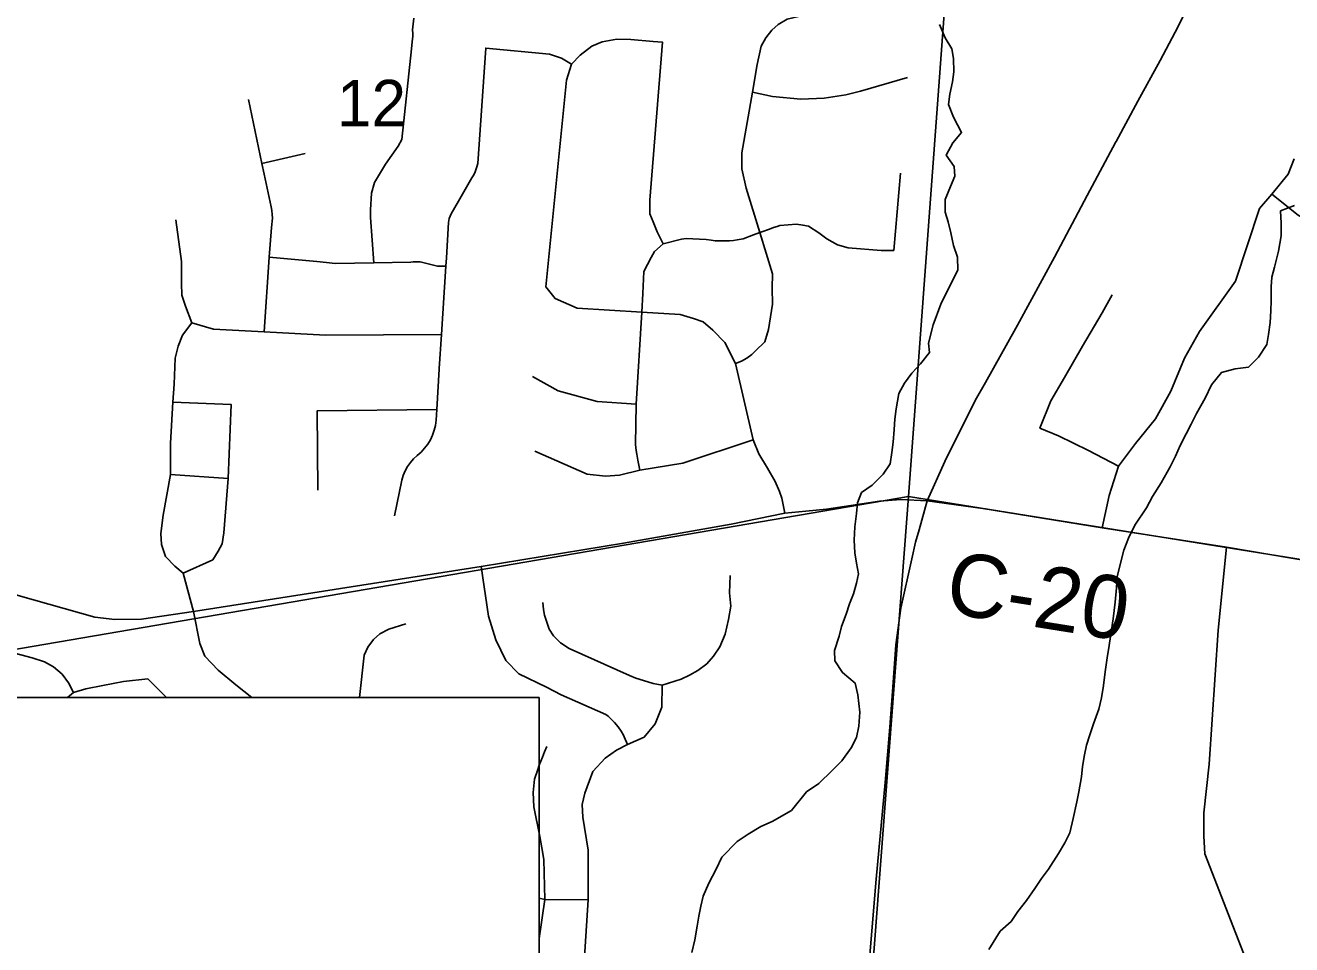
# Model space of a CAD drawing. Extents: x 0 to 34, y 0 to 22.
# Drawn here: x 3.964 to 5.107, y 19.14 to 19.97 of the extents above; entities that cross this region are included whole.
import ezdxf

# ---------------------------------------------------------------- set-up
doc = ezdxf.new("R2010")
doc.units = 0
for name, color, linetype in [('GM_X_County_Road', 7, 'Continuous'), ('GM_X_County_Road_Text', 7, 'Continuous'), ('GM_X_Minor_River', 7, 'Continuous'), ('GM_X_Section', 7, 'Continuous'), ('GM_X_Section_Text', 7, 'Continuous'), ('GM_X_State_Route', 7, 'Continuous'), ('GM_X_Township_Road', 7, 'Continuous'), ('SH_Text', 7, 'Continuous')]:
    doc.layers.add(name, color=color, linetype=linetype)

msp = doc.modelspace()

# ---------------------------------------------------------------- linework, layer by layer
at = {"layer": 'GM_X_County_Road'}
for points in [[(4.6684, 19.5314), (4.6871, 19.5332), (4.7349, 19.5405), (4.7541, 19.5419), (4.778, 19.5406)], [(4.778, 19.5406), (4.8282, 19.5339), (4.9358, 19.5164), (5.0482, 19.4989)], [(3.722, 19.5159), (3.723, 19.5156), (3.7934, 19.4984), (3.9, 19.4714), (4.0267, 19.4358), (4.0449, 19.4335), (4.0688, 19.4339), (4.1158, 19.4408), (4.3754, 19.4815), (4.5038, 19.5025), (4.601, 19.5196), (4.6497, 19.5297), (4.6684, 19.5314)], [(5.161, 18.7471), (5.1674, 18.7519), (5.169, 18.7561), (5.1733, 18.8123), (5.1758, 18.8558), (5.1727, 18.8724), (5.1612, 18.8948), (5.1426, 18.9289), (5.0287, 19.2221), (5.0277, 19.238), (5.0278, 19.2591), (5.0324, 19.303), (5.0407, 19.4239), (5.0482, 19.4989)], [(5.0482, 19.4989), (5.2615, 19.4628), (5.4086, 19.4362), (5.7556, 19.3822), (5.814, 19.3715), (5.9052, 19.3498), (5.9474, 19.3395), (6.067, 19.3122), (6.1386, 19.2955), (6.1993, 19.2816), (6.3594, 19.2439), (6.4061, 19.2324), (6.5388, 19.202)]]:
    msp.add_lwpolyline(points, dxfattribs=at)
at = {"layer": 'GM_X_Minor_River'}
for points in [[(4.5811, 19.1955), (4.5876, 19.2083), (4.5928, 19.2191), (4.6066, 19.2331), (4.6166, 19.2397), (4.6279, 19.2469), (4.6382, 19.2512), (4.6556, 19.2613), (4.6691, 19.278), (4.6803, 19.2856), (4.6924, 19.2974), (4.7011, 19.3059), (4.7094, 19.3178), (4.7142, 19.3272), (4.7164, 19.3374), (4.7172, 19.3499), (4.7154, 19.3655), (4.713, 19.3762), (4.7015, 19.3857), (4.6946, 19.3962), (4.6945, 19.4057), (4.6987, 19.4185), (4.7008, 19.4272), (4.705, 19.4384), (4.7079, 19.4479), (4.7116, 19.4569), (4.7141, 19.4663), (4.7159, 19.475), (4.7143, 19.4845), (4.7127, 19.4937), (4.7122, 19.5051), (4.7126, 19.5173), (4.7141, 19.5294), (4.7151, 19.5389), (4.7188, 19.5482), (4.7285, 19.5548), (4.7383, 19.5648), (4.7447, 19.5741), (4.7461, 19.5843), (4.7472, 19.5938), (4.7483, 19.6051), (4.7489, 19.6146), (4.7499, 19.6237), (4.7523, 19.6377), (4.7575, 19.647), (4.7642, 19.656), (4.7721, 19.6645), (4.78, 19.6745), (4.7791, 19.6832), (4.7833, 19.6995), (4.7904, 19.7183), (4.8001, 19.7377), (4.8057, 19.749), (4.8053, 19.7607), (4.8018, 19.7711), (4.7995, 19.7826), (4.7971, 19.7925), (4.7943, 19.8014), (4.7943, 19.8128), (4.7992, 19.8244), (4.8029, 19.8338), (4.8024, 19.8426), (4.7951, 19.8527), (4.8011, 19.8639), (4.809, 19.8731), (4.8018, 19.8871), (4.7972, 19.8986), (4.7986, 19.9077), (4.8008, 19.919), (4.8022, 19.9281), (4.8018, 19.9399), (4.8002, 19.9487), (4.7944, 19.9587), (4.7891, 19.9707)], [(4.8336, 19.1357), (4.844, 19.1522), (4.8538, 19.161), (4.8597, 19.1699), (4.8676, 19.1799), (4.8752, 19.1907), (4.8811, 19.1997), (4.8875, 19.2082), (4.8966, 19.2224), (4.9022, 19.2321), (4.9067, 19.2411), (4.9097, 19.2539), (4.9132, 19.269), (4.915, 19.2781), (4.9173, 19.2917), (4.9183, 19.3008), (4.9201, 19.3114), (4.9219, 19.3201), (4.9249, 19.3295), (4.9282, 19.3393), (4.9328, 19.3528), (4.9354, 19.363), (4.9372, 19.374), (4.9387, 19.3864), (4.9406, 19.3989), (4.9424, 19.4103), (4.9444, 19.4243), (4.9458, 19.4341), (4.9478, 19.4493), (4.9489, 19.4622), (4.9496, 19.472), (4.9526, 19.4845), (4.9556, 19.4962), (4.9597, 19.5071), (4.9654, 19.5187), (4.9761, 19.5343), (4.9814, 19.5448), (4.9893, 19.5571), (4.9974, 19.5713), (5.0022, 19.581), (5.0063, 19.5908), (5.0119, 19.6013), (5.0164, 19.6099), (5.0212, 19.6196), (5.0288, 19.6334), (5.0345, 19.6454), (5.0436, 19.6565), (5.0559, 19.66), (5.0681, 19.6615), (5.0771, 19.6703), (5.0846, 19.6819), (5.086, 19.691), (5.0875, 19.7016), (5.0882, 19.7122), (5.0884, 19.7213), (5.0884, 19.7339), (5.0891, 19.7426), (5.0916, 19.7516), (5.0951, 19.766), (5.0974, 19.78), (5.0974, 19.7914), (5.0969, 19.8024), (5.1096, 19.8073)], [(4.5656, 19.1329), (4.5682, 19.1446), (4.5705, 19.1567), (4.5719, 19.1658), (4.5737, 19.1749), (4.5758, 19.1839), (4.5811, 19.1955)]]:
    msp.add_lwpolyline(points, dxfattribs=at)
at = {"layer": 'GM_X_Section'}
for points in [[(4.818, 20.3144), (4.7613, 19.5448), (3.7257, 19.3674), (3.806, 20.3918)], [(4.818, 20.3144), (5.8084, 20.2412), (5.7435, 19.3869), (4.7613, 19.5448)]]:
    msp.add_lwpolyline(points, close=True, dxfattribs=at)
for points in [[(3.7253, 19.3633), (3.7257, 19.3674), (4.7613, 19.5448), (4.6831, 18.5192), (3.6423, 18.3609), (3.6787, 18.801)], [(5.1102, 18.4472), (4.6831, 18.5192), (4.7613, 19.5448), (5.7435, 19.3869), (5.6931, 18.7255)]]:
    msp.add_lwpolyline(points, dxfattribs=at)
at = {"layer": 'GM_X_State_Route'}
for points in [[(4.9486, 19.8652), (4.9682, 19.9015), (4.9884, 19.9383), (5.0045, 19.9689), (5.014, 19.9878)], [(4.8595, 19.6992), (4.8929, 19.7608), (4.9224, 19.8164), (4.9481, 19.8643), (4.9486, 19.8652)], [(4.8306, 19.6476), (4.8581, 19.6966), (4.8595, 19.6992)], [(4.778, 19.5406), (4.7939, 19.5762), (4.8214, 19.6313), (4.8306, 19.6476)], [(4.7442, 19.3363), (4.7468, 19.3686), (4.7497, 19.4108), (4.7543, 19.4439), (4.7643, 19.4885), (4.7676, 19.5033), (4.7709, 19.5147), (4.778, 19.5406)], [(4.7164, 18.9842), (4.7189, 19.0149), (4.7243, 19.1056), (4.7319, 19.1993), (4.7401, 19.2864), (4.7442, 19.3363)]]:
    msp.add_lwpolyline(points, dxfattribs=at)
at = {"layer": 'GM_X_Township_Road'}
for p, q in [((4.1776, 19.8454), (4.2166, 19.8544)), ((4.095, 19.5644), (4.1471, 19.5608)), ((4.0916, 19.3633), (4.0747, 19.3801)), ((4.3259, 19.3633), (4.3259, 19.3636)), ((4.4279, 19.1457), (4.433, 19.181))]:
    msp.add_line(p, q, dxfattribs=at)
for points in [[(4.605, 19.6647), (4.6104, 19.6668), (4.6153, 19.6695), (4.6197, 19.6728), (4.6231, 19.6762), (4.6314, 19.6844), (4.6347, 19.6955), (4.6384, 19.7182), (4.638, 19.7327), (4.6384, 19.7457), (4.627, 19.7829), (4.6147, 19.8229), (4.6106, 19.8404), (4.6106, 19.855), (4.6203, 19.9096), (4.6246, 19.9345), (4.6283, 19.9512), (4.6324, 19.9586), (4.6377, 19.9655), (4.6435, 19.9708), (4.6516, 19.9754), (4.662, 19.978), (4.6878, 19.9824), (4.7572, 19.9878)], [(4.2786, 19.7557), (4.2756, 19.7964), (4.2756, 19.8033), (4.2765, 19.8185), (4.2792, 19.8282), (4.2892, 19.8448), (4.3007, 19.8609), (4.304, 19.8669), (4.3126, 19.9489), (4.3131, 19.9552), (4.3138, 19.9601), (4.3137, 19.9627), (4.3134, 19.966), (4.3146, 19.9765)], [(4.6497, 19.5297), (4.6467, 19.5431), (4.6447, 19.5493), (4.6408, 19.5582), (4.6338, 19.5701), (4.6262, 19.5832), (4.6211, 19.5959), (4.605, 19.6647), (4.5953, 19.6837), (4.5846, 19.6948), (4.5757, 19.7022), (4.5671, 19.7052), (4.5552, 19.7089), (4.5204, 19.7111), (4.462, 19.7148), (4.4422, 19.7234), (4.4338, 19.7338), (4.4525, 19.9206), (4.457, 19.935), (4.4647, 19.9432), (4.4755, 19.9513), (4.4847, 19.9551), (4.498, 19.9576), (4.5105, 19.9572), (4.5308, 19.9554), (4.539, 19.9549), (4.5278, 19.8122), (4.5278, 19.7999), (4.5307, 19.7925), (4.5344, 19.7836), (4.5396, 19.7728)], [(4.2973, 19.5272), (4.3038, 19.5593), (4.3051, 19.5636), (4.3069, 19.5677), (4.309, 19.5717), (4.3116, 19.5753), (4.3145, 19.5787), (4.3178, 19.5818), (4.3213, 19.5848), (4.3245, 19.5882), (4.3273, 19.5919), (4.3297, 19.5958), (4.3317, 19.6), (4.3332, 19.6044), (4.3342, 19.6089), (4.3348, 19.6135), (4.3354, 19.6232), (4.3375, 19.6597), (4.3376, 19.6602), (4.3397, 19.691), (4.3436, 19.7525), (4.3443, 19.7601), (4.346, 19.792), (4.3467, 19.7955), (4.3483, 19.7999), (4.3551, 19.8114), (4.3658, 19.8302), (4.3671, 19.8322), (4.3688, 19.8349), (4.37, 19.8378), (4.3713, 19.8414), (4.3724, 19.8452), (4.3796, 19.9495), (4.4372, 19.9441), (4.4479, 19.9403), (4.457, 19.935)], [(4.6203, 19.9096), (4.6385, 19.9057), (4.664, 19.9034), (4.685, 19.9042), (4.7045, 19.9072), (4.7179, 19.9105), (4.7602, 19.9228)], [(4.1796, 19.6934), (4.1843, 19.7606), (4.1862, 19.7874), (4.1871, 19.7958), (4.187, 19.7991), (4.1867, 19.8027), (4.1859, 19.806), (4.1797, 19.8357), (4.1776, 19.8454), (4.1654, 19.9029)], [(4.9358, 19.5164), (4.9424, 19.5455), (4.9507, 19.5719), (4.9661, 19.5926), (4.9842, 19.6149), (4.9978, 19.6398), (5.0103, 19.6696), (5.0238, 19.6937), (5.0563, 19.739), (5.0778, 19.8046), (5.0891, 19.8175), (5.1038, 19.8356), (5.1091, 19.8495)], [(4.5188, 19.5685), (4.5169, 19.5776), (4.5159, 19.5829), (4.5154, 19.5862), (4.5149, 19.5917), (4.5155, 19.6279), (4.5204, 19.7111), (4.5214, 19.7279), (4.5222, 19.7479), (4.5289, 19.7605), (4.5318, 19.7657), (4.5396, 19.7728), (4.5562, 19.7769), (4.5605, 19.7775), (4.5787, 19.7766), (4.583, 19.776), (4.5866, 19.7756), (4.5912, 19.7754), (4.5932, 19.7754), (4.5964, 19.7754), (4.5996, 19.7756), (4.6031, 19.7759), (4.6064, 19.7763), (4.6118, 19.7773), (4.6212, 19.7808), (4.627, 19.7829), (4.6288, 19.7836), (4.6358, 19.7861), (4.6393, 19.7874), (4.6425, 19.7885), (4.645, 19.7894), (4.66, 19.7904), (4.6658, 19.7897), (4.671, 19.7886), (4.6803, 19.7828), (4.6874, 19.7772), (4.697, 19.7718), (4.7067, 19.7692), (4.7365, 19.7668), (4.7478, 19.7668), (4.7538, 19.8365)], [(5.0891, 19.8175), (5.1127, 19.7987), (5.1356, 19.7855), (5.1715, 19.7763), (5.246, 19.7628)], [(4.1144, 19.7013), (4.1088, 19.7164), (4.1052, 19.7264), (4.1049, 19.7373), (4.1049, 19.7567), (4.0999, 19.7945)], [(4.1843, 19.7606), (4.2273, 19.7568), (4.2358, 19.7558), (4.2437, 19.7551), (4.2786, 19.7557), (4.3119, 19.7563), (4.314, 19.7565), (4.3161, 19.7566), (4.3181, 19.7566), (4.3204, 19.7565), (4.336, 19.7526), (4.3436, 19.7525)], [(4.9507, 19.5719), (4.9236, 19.5861), (4.8964, 19.5993), (4.8797, 19.6064), (4.8895, 19.631), (4.9019, 19.6522), (4.9181, 19.6805), (4.9359, 19.7104), (4.9449, 19.7266)], [(4.1158, 19.4408), (4.1065, 19.4754), (4.099, 19.4818), (4.0905, 19.4906), (4.0869, 19.5012), (4.0863, 19.5112), (4.0884, 19.5278), (4.095, 19.5644), (4.095, 19.5929), (4.0971, 19.6298), (4.0985, 19.6462), (4.0994, 19.6694), (4.1021, 19.6804), (4.1058, 19.6904), (4.1144, 19.7013)], [(4.1144, 19.7013), (4.1339, 19.6958), (4.1796, 19.6934), (4.235, 19.6904), (4.3397, 19.691)], [(4.4218, 19.6529), (4.445, 19.6401), (4.4802, 19.6304), (4.5155, 19.6279)], [(4.1065, 19.4754), (4.1332, 19.4875), (4.1382, 19.4954), (4.1418, 19.5018), (4.1433, 19.5118), (4.1471, 19.5608), (4.15, 19.6277), (4.0971, 19.6298)], [(4.2282, 19.5504), (4.2275, 19.6221), (4.3354, 19.6232)], [(4.4238, 19.5856), (4.4713, 19.5648), (4.4876, 19.5629), (4.5003, 19.564), (4.5188, 19.5685), (4.5575, 19.5748), (4.6211, 19.5959)], [(4.5076, 19.3207), (4.5045, 19.3278), (4.5038, 19.3291), (4.5017, 19.3328), (4.4991, 19.3366), (4.4957, 19.3408), (4.4926, 19.344), (4.49, 19.3463), (4.488, 19.3478), (4.4476, 19.3657), (4.4346, 19.3725), (4.4094, 19.3845), (4.3979, 19.3966), (4.3888, 19.4153), (4.3821, 19.4365), (4.3754, 19.4815)], [(4.4311, 19.4491), (4.4317, 19.4427), (4.4328, 19.4376), (4.4344, 19.4321), (4.4368, 19.425), (4.4408, 19.4188), (4.447, 19.4126), (4.4548, 19.4073), (4.5093, 19.383), (4.5151, 19.3806), (4.5221, 19.3787), (4.5307, 19.376), (4.5388, 19.3745), (4.556, 19.3799), (4.5636, 19.3834), (4.571, 19.3876), (4.5791, 19.3937), (4.5853, 19.4004), (4.591, 19.4089), (4.5958, 19.4203), (4.5987, 19.4335), (4.6007, 19.4458), (4.5996, 19.4578), (4.6002, 19.4734)], [(3.7849, 19.4474), (3.8838, 19.4231), (3.9279, 19.4102), (3.9703, 19.3989), (3.9814, 19.3954), (3.9894, 19.3909), (3.9973, 19.3844), (4.0031, 19.3765), (4.0077, 19.3677)], [(4.1685, 19.3633), (4.154, 19.3747), (4.138, 19.388), (4.1261, 19.4005), (4.1215, 19.412), (4.1158, 19.4408)], [(4.2658, 19.3633), (4.2698, 19.4013), (4.2731, 19.4087), (4.2783, 19.4156), (4.2841, 19.4206), (4.2922, 19.4248), (4.3076, 19.4296)], [(4.0023, 19.3633), (4.0077, 19.3677), (4.0186, 19.3711), (4.034, 19.374), (4.0528, 19.3776), (4.0747, 19.3801)], [(4.4683, 19.1242), (4.472, 19.1807), (4.472, 19.2255), (4.4672, 19.2552), (4.4667, 19.2667), (4.469, 19.277), (4.4763, 19.2964), (4.4873, 19.3085), (4.4975, 19.3157), (4.5076, 19.3207), (4.5226, 19.3275), (4.5325, 19.3393), (4.5385, 19.3545), (4.5388, 19.3745)], [(4.433, 19.181), (4.4321, 19.217), (4.4303, 19.2276), (4.4285, 19.2376), (4.423, 19.2646), (4.4224, 19.2776), (4.4235, 19.2895), (4.4266, 19.2981), (4.4279, 19.3022), (4.4307, 19.3093), (4.4326, 19.3141), (4.4347, 19.3189)], [(4.4279, 19.1822), (4.433, 19.181), (4.472, 19.1807)]]:
    msp.add_lwpolyline(points, dxfattribs=at)
at = {"layer": 'SH_Text'}
msp.add_lwpolyline([(4.4279, 19.3633), (2.1739, 19.3633), (2.1739, 18.801), (4.4279, 18.801)], close=True, dxfattribs=at)

# ---------------------------------------------------------------- texts
at = {"layer": 'GM_X_County_Road_Text'}
msp.add_text('C-20', height=0.05682, rotation=350.9156, dxfattribs=at).set_placement((4.7926, 19.4401))
at = {"layer": 'GM_X_Section_Text'}
msp.add_text('12', height=0.04186, rotation=0, dxfattribs=at).set_placement((4.2454, 19.8789))

doc.saveas('drawing.dxf')
